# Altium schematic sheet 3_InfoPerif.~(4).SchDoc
size 414 x 293 mm; SheetNumber: 3; SheetTotal: 4
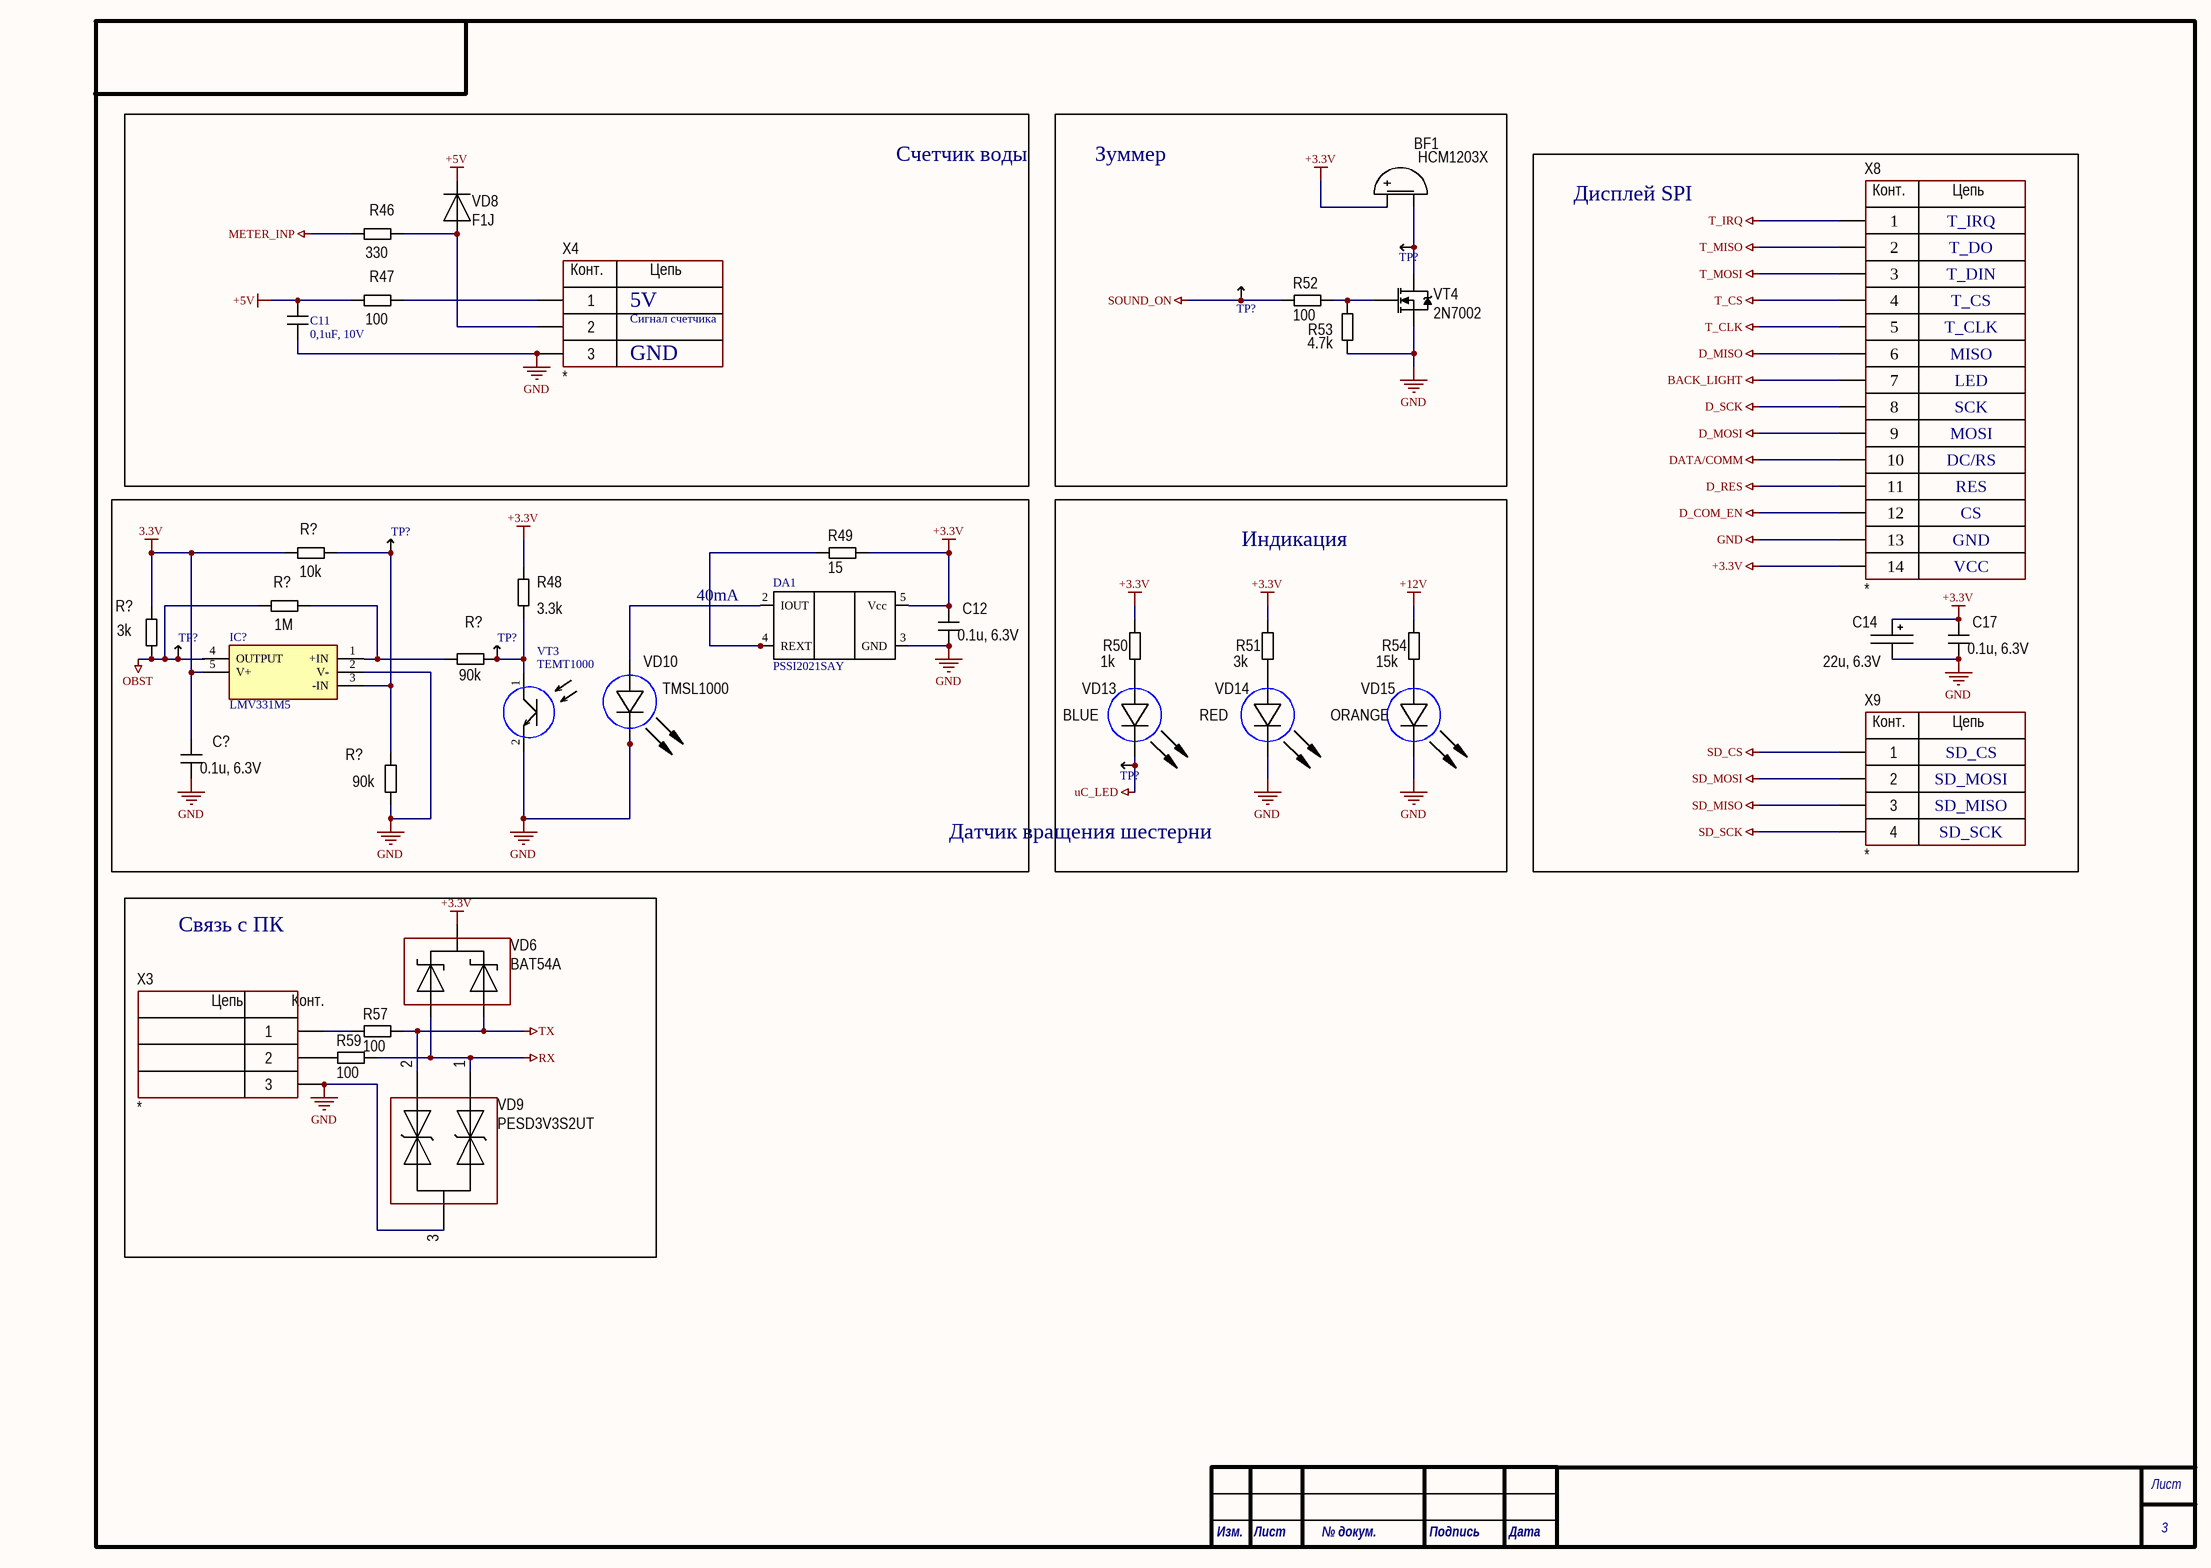
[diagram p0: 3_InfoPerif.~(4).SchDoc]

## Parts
(Parts that share a designator on the sheet are numbered #1, #2 ... from top to bottom, then left to right.)
BF1  HCM1203X  [BUZ: AI-1223-TWT-3V-2-R]
C11  0,1uF, 10V  [C_0603]
C12  0.1u, 6.3V  [CH0805C]
C14  22u, 6.3V  [TANTAL_B]
C17  0.1u, 6.3V  [CH0805C]
C?  0.1u, 6.3V  [CH0805C]
DA1  PSSI2021SAY  [SOT353]
IC?  LMV331M5  [SOT95P280X145-5N]
R46  330  [CH0805R]
R47  100  [CH2512R]
R48  3.3k  [CH0805R]
R49  15  [CH0805R]
R50  1k  [CH0805R]
R51  3k  [CH0805R]
R52  100  [CH0805R]
R53  4.7k  [CH0805R]
R54  15k  [CH0805R]
R57  100  [CH0805R]
R59  100  [CH0805R]
R?#1  10k  [CH0805R]
R?#2  1M  [CH0805R]
R?#3  90k  [CH0805R]
R?#4  3k  [CH0805R]
R?#5  90k  [CH0805R]
TP?#1  TestPoint  (value not drawn)
TP?#2  TestPoint  (value not drawn)
TP?#3  TestPoint  (value not drawn)
TP?#4  TestPoint  (value not drawn)
TP?#5  TestPoint  (value not drawn)
TP?#6  TestPoint  (value not drawn)
VD6  BAT54A  [SOT23_123]
VD8  F1J  [SOD123F]
VD9  PESD3V3S2UT  [SOT23_132]
VD10  TMSL1000  [TSML1000]
VD13  BLUE  [CH0603LB]
VD14  RED  [CH0603LB]
VD15  ORANGE  [CH0603LB]
VT3  TEMT1000  [TEMT1000]
VT4  2N7002  [SOT23_123]
X3  *  [CON: CWF-3]
X4  *  [CON: CWF-3]
X8  *  [DS1024-14]
X9  *  [DS1023-4]

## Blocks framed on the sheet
Зуммер: BF1 R52 R53 TP?#1 TP?#2 VT4
Дисплей SPI: C14 C17 X8 X9
Датчик вращения шестерни: C12 C? DA1 IC? R48 R49 R?#1-R?#5 TP?#3-TP?#5 VD10 VT3
Индикация: R50 R51 R54 TP?#6 VD13-VD15
Связь с ПК: R57 R59 VD6 VD9 X3

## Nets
3.3V: C?.2 IC?.5(V+) R?#1.2 R?#4.2
+3.3V: BF1.1(+) C12.2 C14.1 C17.2 R48.2 R49.2 R50.2 R51.2 VD6.2 X8.14
+5V: C11.2 R47.1 VD8.2
+12V: R54.2
BACK_LIGHT: X8.7
D_COM_EN: X8.12
D_MISO: X8.6
D_MOSI: X8.9
D_RES: X8.11
D_SCK: X8.8
DATA/COMM: X8.10
GND: C11.1 C12.1 C14.2 C17.1 C?.1 DA1.3(GND) IC?.2(V-) R53.1 R?#5.1 VD9.3 VD10.2(C) VD14.2(C) VD15.2(C) VT3.2 VT4.3(S) X3.3 X4.3 X8.13
METER_INP: R46.1
OBST: IC?.4(OUTPUT) R?#2.2 R?#4.1 TP?#4.0
RX: R59.2 VD6.3 VD9.1
SD_CS: X9.1
SD_MISO: X9.3
SD_MOSI: X9.2
SD_SCK: X9.4
SOUND_ON: R52.2 TP?#2.0
T_CLK: X8.5
T_CS: X8.4
T_IRQ: X8.1
T_MISO: X8.2
T_MOSI: X8.3
TX: R57.2 VD6.1 VD9.2
uC_LED: TP?#6.0 VD13.2(C)
NetBF1_2: BF1.2(-) TP?#1.0 VT4.2(D)
NetDA1_2: DA1.2(IOUT) VD10.1(A)
NetDA1_4: DA1.4(REXT) R49.1
NetIC?_1: IC?.1(+IN) R?#2.1 R?#3.2
NetIC?_3: IC?.3(-IN) R?#1.1 R?#5.2 TP?#3.0
NetR46_2: R46.2 VD8.1 X4.2
NetR47_2: R47.2 X4.1
NetR48_1: R48.1 R?#3.1 TP?#5.0 VT3.1
NetR50_1: R50.1 VD13.1(A)
NetR51_1: R51.1 VD14.1(A)
NetR52_1: R52.1 R53.2 VT4.1(G)
NetR54_1: R54.1 VD15.1(A)
NetR57_1: R57.1 X3.1
NetR59_1: R59.1 X3.2

Not connected (* = marked no-connect by the designer): DA1 5(Vcc)

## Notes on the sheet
- Счетчик воды
- T_IRQ
- 5V
- T_DO
- T_DIN
- T_CS
- GND
- Сигнал счетчика
- T_CLK
- MISO
- LED
- SCK
- MOSI
- DC/RS
- RES
- CS
- VCC
- 40mA
- SD_CS
- SD_MOSI
- SD_MISO
- SD_SCK

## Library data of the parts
BF1 = Buzzer: Manufacturer: PUI Audio, Inc.; Model: AI-1223-TWT-3V-2-R
C11 = C_SMD
C12 C? = Capacitor: 0805
C14 = TantalCap
C17 = Capacitor
DA1 = PSSI2021SAY: Iout = 0.617/Rext + 15 µA
IC? = LMV331M5: Integrated Circuit; Manufacturer_Name: Texas Instruments
R46 R47 R50-R54 R57 R59 R?#1-R?#5 = Resistor
R48 R49 = Resistor: 0805
VD6 = Diod Schottky Array v.1
VD8 = Diod
VD9 = TVS Array
VD10 VD13-VD15 = LED_1
VT4 = N-chanel: Mosfet
X3 X4 = 3-Connector
X8 = 14-Connector
X9 = 4-Connector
